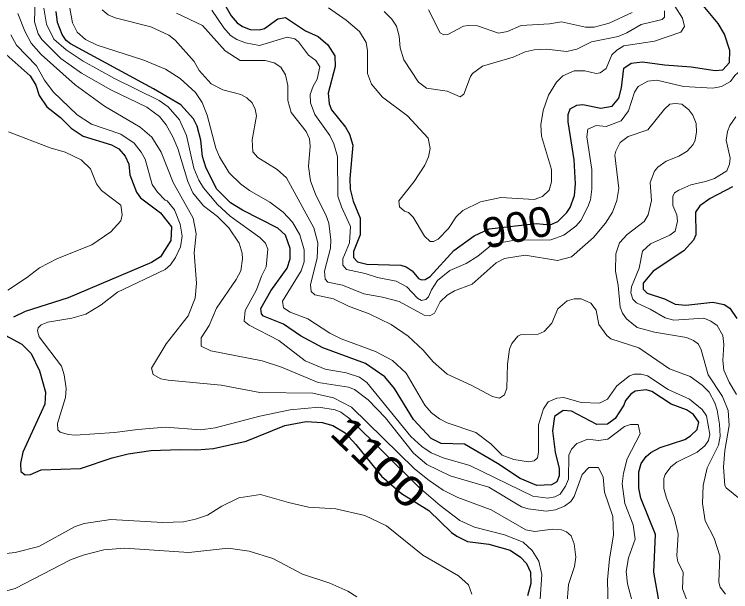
# Model space of a CAD drawing. Extents: x 265 to 291.4, y 7731.5 to 7759.6.
# Drawn here: x 283.424 to 285.338, y 7746.284 to 7747.826 of the extents above; entities that cross this region are included whole.
import ezdxf
from ezdxf.enums import TextEntityAlignment as Align

# ---------------------------------------------------------------- set-up
doc = ezdxf.new("R2010")
doc.units = 0
doc.header["$LTSCALE"] = 0.032
for name, color, linetype, lineweight in [('1', 7, 'Continuous', 25), ('2', 7, 'Continuous', 13), ('61', 7, 'Continuous', 13)]:
    doc.layers.add(name, color=color, linetype=linetype, lineweight=lineweight)

msp = doc.modelspace()

# ---------------------------------------------------------------- linework, layer by layer
at = {"layer": '1'}
for points in [[(283.9682, 7747.8833), (284.0032, 7747.8221), (284.0191, 7747.8037), (284.0334, 7747.7934), (284.0541, 7747.7855), (284.078, 7747.7847), (284.0923, 7747.7886), (284.1281, 7747.8141), (284.1488, 7747.8173), (284.2021, 7747.7823), (284.2355, 7747.7664), (284.2617, 7747.7449), (284.28, 7747.7155), (284.2816, 7747.6868), (284.2625, 7747.6153), (284.2649, 7747.5866), (284.2713, 7747.5707), (284.3087, 7747.5246), (284.3198, 7747.5055), (284.3286, 7747.4768), (284.3206, 7747.3877), (284.3214, 7747.3591), (284.3293, 7747.3273), (284.3484, 7747.2811), (284.3484, 7747.2366), (284.3301, 7747.1921), (284.3301, 7747.1761), (284.3405, 7747.165), (284.366, 7747.1586), (284.4567, 7747.1562), (284.471, 7747.1515), (284.4869, 7747.1411), (284.5036, 7747.1204), (284.5115, 7747.1165), (284.5219, 7747.118), (284.5354, 7747.126), (284.5982, 7747.1952), (284.6523, 7747.2342), (284.6932, 7747.253), (284.8184, 7747.2676), (284.8555, 7747.2636), (284.876, 7747.2722), (284.9005, 7747.2962), (284.9093, 7747.3098), (284.9212, 7747.3416), (284.9236, 7747.3734), (284.9196, 7747.4371), (284.9037, 7747.5389), (284.9037, 7747.5588), (284.9093, 7747.5739), (284.9276, 7747.5834), (284.9435, 7747.585), (284.9912, 7747.5755), (285.0214, 7747.581), (285.0397, 7747.6017), (285.0469, 7747.6296), (285.0524, 7747.6821), (285.0724, 7747.6956), (285.1026, 7747.6995), (285.1615, 7747.6908), (285.233, 7747.686), (285.2967, 7747.6757), (285.3174, 7747.6781), (285.3356, 7747.6972), (285.3364, 7747.7298), (285.3221, 7747.7728), (285.3046, 7747.8014), (285.2513, 7747.8666)], [(285.1479, 7746.2502), (285.1328, 7746.3361), (285.1376, 7746.4363), (285.0986, 7746.5334), (285.093, 7746.5604), (285.093, 7746.6034), (285.0994, 7746.6257), (285.1129, 7746.6448), (285.1248, 7746.6551), (285.1495, 7746.6686), (285.2163, 7746.6901), (285.2314, 7746.6996), (285.2489, 7746.7171), (285.2537, 7746.7362), (285.2394, 7746.7569), (285.2203, 7746.7696), (285.179, 7746.7847), (285.128, 7746.8182), (285.1121, 7746.8229), (285.0835, 7746.8197), (285.0716, 7746.811), (285.0572, 7746.7943), (285.0532, 7746.7823), (285.0294, 7746.7458), (285.0095, 7746.7314), (284.9809, 7746.7306), (284.9133, 7746.7656), (284.891, 7746.7672), (284.8679, 7746.7514), (284.8623, 7746.7132), (284.8695, 7746.6559), (284.8798, 7746.6129), (284.8798, 7746.593), (284.8735, 7746.5771), (284.8592, 7746.5692), (284.8202, 7746.5676), (284.7756, 7746.5859), (284.7152, 7746.6256), (284.6269, 7746.6773), (284.5648, 7746.6797), (284.5378, 7746.6925), (284.4908, 7746.7434), (284.4399, 7746.8261), (284.4137, 7746.8572), (284.362, 7746.8929), (284.2482, 7746.9351), (284.1886, 7746.9669), (284.1432, 7746.9987), (284.0899, 7747.0194), (284.0843, 7747.0258), (284.0827, 7747.0401), (284.109, 7747.087), (284.1527, 7747.1475), (284.1607, 7747.173), (284.1607, 7747.2), (284.1488, 7747.2358), (284.1281, 7747.2549), (284.0334, 7747.3026), (284.0016, 7747.3225), (283.9642, 7747.3599), (283.9356, 7747.418), (283.9268, 7747.4466), (283.9221, 7747.4896), (283.9125, 7747.5269), (283.9022, 7747.5468), (283.8688, 7747.5842), (283.7956, 7747.6272), (283.5737, 7747.7473), (283.5625, 7747.756), (283.5514, 7747.772), (283.5386, 7747.8046), (283.5355, 7747.8332)], [(283.4018, 7747.7187), (283.4655, 7747.6614), (283.4814, 7747.6367), (283.4901, 7747.6089), (283.5108, 7747.5787), (283.5466, 7747.55), (283.5752, 7747.5221), (283.6071, 7747.5007), (283.6834, 7747.4776), (283.7025, 7747.4665), (283.72, 7747.4474), (283.7296, 7747.4259), (283.7319, 7747.3973), (283.7502, 7747.3512), (283.7606, 7747.336), (283.8147, 7747.2954), (283.8441, 7747.2581), (283.8417, 7747.2215), (283.8139, 7747.1785), (283.79, 7747.1626), (283.5673, 7747.0687), (283.4528, 7747.0321), (283.4209, 7747.017)], [(285.3436, 7747.3654), (285.284, 7747.3344), (285.2561, 7747.3145), (285.2442, 7747.2978), (285.245, 7747.2366), (285.2394, 7747.2223), (285.2132, 7747.1944), (285.1312, 7747.1403), (285.1042, 7747.1077), (285.1042, 7747.0918), (285.1153, 7747.0814), (285.1615, 7747.0663), (285.1901, 7747.052), (285.2187, 7747.0488), (285.2903, 7747.0568), (285.3206, 7747.0512), (285.3365, 7747.0409), (285.3547, 7747.0131)], [(283.3987, 7746.9685), (283.4432, 7746.9446), (283.4686, 7746.92), (283.4909, 7746.8739), (283.5068, 7746.8166), (283.5052, 7746.7848), (283.4464, 7746.6559), (283.44, 7746.6257), (283.4408, 7746.605), (283.4527, 7746.5954), (283.4671, 7746.597), (283.4957, 7746.6089), (283.6007, 7746.6129), (283.685, 7746.6416), (283.728, 7746.6519), (283.7884, 7746.6606), (283.8664, 7746.6638), (283.911, 7746.6622), (283.9555, 7746.6662), (284.043, 7746.6861), (284.1464, 7746.7275), (284.2037, 7746.7386), (284.2466, 7746.7354), (284.2753, 7746.7275), (284.3079, 7746.7076), (284.3368, 7746.6764), (284.4052, 7746.592), (284.4583, 7746.5462), (284.5314, 7746.5007), (284.5919, 7746.4419), (284.6062, 7746.4315), (284.6348, 7746.418), (284.6921, 7746.4109), (284.7494, 7746.3942), (284.7764, 7746.3759), (284.7923, 7746.3592), (284.8035, 7746.3353), (284.8043, 7746.3051), (284.7955, 7746.2725)]]:
    msp.add_lwpolyline(points, dxfattribs=at)
at = {"layer": '2'}
for points in [[(284.7796, 7746.5103), (284.6921, 7746.5628), (284.5887, 7746.593), (284.5258, 7746.6233), (284.4908, 7746.6535), (284.4153, 7746.7482), (284.3691, 7746.7959), (284.3326, 7746.8237), (284.3166, 7746.8301), (284.2355, 7746.8428), (284.1377, 7746.8834), (284.086, 7746.9001), (283.9491, 7746.9271), (283.9229, 7746.9399), (283.9229, 7746.9622), (283.9443, 7746.9948), (283.9642, 7747.0409), (284.0167, 7747.1173), (284.0287, 7747.1411), (284.0334, 7747.173), (284.0326, 7747.1881), (284.0247, 7747.2143), (283.9968, 7747.2557), (283.9666, 7747.2859), (283.9292, 7747.3145), (283.9006, 7747.3496), (283.8871, 7747.379), (283.8608, 7747.4673), (283.8473, 7747.4991), (283.829, 7747.5309), (283.8115, 7747.5532), (283.7781, 7747.5779), (283.6811, 7747.624), (283.6031, 7747.6685), (283.5482, 7747.7083), (283.4973, 7747.7584), (283.4869, 7747.7743), (283.4774, 7747.8062), (283.4798, 7747.9016)], [(283.5021, 7747.8428), (283.5092, 7747.7998), (283.5291, 7747.76), (283.5625, 7747.7314), (283.6071, 7747.7011), (283.6914, 7747.6542), (283.8107, 7747.5954), (283.8346, 7747.5786), (283.8648, 7747.5444), (283.8839, 7747.5023), (283.9038, 7747.4148), (283.9165, 7747.383), (283.9292, 7747.3623), (283.9666, 7747.3177), (284.0008, 7747.2867), (284.0796, 7747.2302), (284.0947, 7747.2143), (284.1011, 7747.1984), (284.0971, 7747.1515), (284.0843, 7747.1268), (284.0708, 7747.0902), (284.0406, 7747.0345), (284.0382, 7747.0067), (284.051, 7746.9956), (284.1305, 7746.9542), (284.2013, 7746.9001), (284.2546, 7746.8778), (284.3103, 7746.8683), (284.3461, 7746.8563), (284.366, 7746.842), (284.4837, 7746.698), (284.5131, 7746.671), (284.5378, 7746.6543), (284.5696, 7746.6408), (284.6412, 7746.6209), (284.8098, 7746.5389), (284.8496, 7746.5334), (284.8687, 7746.5366), (284.883, 7746.5437), (284.8973, 7746.5652), (284.9045, 7746.5843), (284.9061, 7746.6479), (284.9133, 7746.6646), (284.9276, 7746.6798), (284.9562, 7746.6909), (284.9849, 7746.6877), (285.0103, 7746.6909), (285.0549, 7746.7251), (285.0708, 7746.7299), (285.0914, 7746.7299), (285.0962, 7746.7052), (285.062, 7746.6384), (285.0517, 7746.6002), (285.0485, 7746.5716), (285.0556, 7746.5191), (285.0779, 7746.4618), (285.0827, 7746.4236), (285.0652, 7746.3743), (285.0588, 7746.3377), (285.0628, 7746.3043), (285.0827, 7746.2279)], [(285.0342, 7746.8333), (285.0087, 7746.7975), (284.988, 7746.7871), (284.9387, 7746.7887), (284.8926, 7746.8022), (284.8735, 7746.8007), (284.8504, 7746.7911), (284.8377, 7746.772), (284.825, 7746.7291), (284.825, 7746.6559), (284.8218, 7746.6416), (284.813, 7746.6328), (284.7979, 7746.6304), (284.7589, 7746.6368), (284.7279, 7746.6487), (284.6977, 7746.679), (284.6571, 7746.7092), (284.5808, 7746.7346), (284.5601, 7746.745), (284.5386, 7746.7617), (284.5211, 7746.7816), (284.471, 7746.8675), (284.4344, 7746.9009), (284.389, 7746.9256), (284.2976, 7746.959), (284.2673, 7746.9741), (284.2077, 7747.0123), (284.1607, 7747.0306), (284.1432, 7747.0417), (284.1408, 7747.06), (284.1902, 7747.1411), (284.1981, 7747.165), (284.1981, 7747.1968), (284.187, 7747.2366), (284.1671, 7747.2708), (284.1424, 7747.2971), (284.1066, 7747.3241), (284.0525, 7747.3551), (284.0279, 7747.3734), (283.9976, 7747.4029), (283.9722, 7747.445), (283.9626, 7747.4689), (283.9388, 7747.5564), (283.9253, 7747.5906), (283.9078, 7747.6168), (283.8672, 7747.655), (283.8274, 7747.6797), (283.7694, 7747.7035), (283.6453, 7747.7441), (283.6134, 7747.7592), (283.5912, 7747.7783), (283.5792, 7747.803), (283.5721, 7747.8428)], [(283.658, 7747.838), (283.6747, 7747.8245), (283.693, 7747.8165), (283.7884, 7747.7926), (283.8362, 7747.7704), (283.8537, 7747.7568), (283.9046, 7747.6996), (283.9173, 7747.6757), (283.9499, 7747.6407), (283.981, 7747.624), (284.0287, 7747.6121), (284.0446, 7747.6033), (284.0589, 7747.5898), (284.0676, 7747.5723), (284.0708, 7747.5548), (284.0589, 7747.4912), (284.0613, 7747.4585), (284.0748, 7747.4434), (284.1257, 7747.4116), (284.1512, 7747.3893), (284.2244, 7747.2557), (284.2347, 7747.2159), (284.2331, 7747.1746), (284.2156, 7747.1046), (284.2172, 7747.0855), (284.2268, 7747.0767), (284.2769, 7747.0656), (284.3166, 7747.0465), (284.3723, 7747.0258), (284.4312, 7746.9971), (284.4765, 7746.9661), (284.5163, 7746.9287), (284.5433, 7746.8977), (284.5808, 7746.8651), (284.6444, 7746.8357), (284.7017, 7746.8046), (284.7208, 7746.8007), (284.7335, 7746.8094), (284.7398, 7746.8277), (284.7422, 7746.8914), (284.747, 7746.9311), (284.7534, 7746.947), (284.7693, 7746.9661), (284.7764, 7746.9701), (284.8242, 7746.9717)], [(285.1615, 7747.5723), (285.1169, 7747.5174), (285.0644, 7747.4999), (285.0429, 7747.484), (285.031, 7747.4609), (285.0286, 7747.4498), (285.0397, 7747.3607), (285.0342, 7747.3289), (285.0222, 7747.2971), (285.0039, 7747.2684), (284.9721, 7747.2302), (284.9133, 7747.1785), (284.8751, 7747.1682), (284.7892, 7747.1825), (284.7335, 7747.1737), (284.7112, 7747.1618), (284.6476, 7747.1053), (284.5998, 7747.087), (284.5808, 7747.0759), (284.5616, 7747.0576), (284.5465, 7747.0274), (284.5346, 7747.0202), (284.5187, 7747.0226), (284.4519, 7747.0584), (284.4073, 7747.0703), (284.358, 7747.0791), (284.3007, 7747.1022), (284.2618, 7747.1109), (284.2546, 7747.1189), (284.253, 7747.1403), (284.2689, 7747.2016), (284.2697, 7747.2239), (284.2641, 7747.2684), (284.2562, 7747.2907), (284.2291, 7747.3432), (284.2148, 7747.3814), (284.21, 7747.4196), (284.214, 7747.4737), (284.2124, 7747.4935), (284.2037, 7747.5126), (284.1631, 7747.5635), (284.1544, 7747.5962), (284.1544, 7747.6359), (284.1488, 7747.6646), (284.1361, 7747.6853), (284.1178, 7747.6964), (284.0939, 7747.7027), (284.0271, 7747.7027), (283.9873, 7747.7282), (283.9261, 7747.7958), (283.8569, 7747.8292)], [(283.9515, 7747.8372), (283.9833, 7747.7903), (284.0016, 7747.7696), (284.0183, 7747.7584), (284.0414, 7747.7497), (284.0788, 7747.7425), (284.1528, 7747.7648), (284.1735, 7747.7608), (284.183, 7747.7528), (284.21, 7747.7171), (284.2291, 7747.7027), (284.2403, 7747.686), (284.2331, 7747.6526), (284.222, 7747.6343), (284.214, 7747.6121), (284.2148, 7747.5898), (284.2267, 7747.558), (284.2673, 7747.5023), (284.2777, 7747.48), (284.2872, 7747.4466), (284.288, 7747.34), (284.2983, 7747.3114), (284.3222, 7747.2589), (284.3198, 7747.2159), (284.3015, 7747.173), (284.3015, 7747.1563), (284.3111, 7747.1443), (284.3612, 7747.134), (284.3946, 7747.1228), (284.4439, 7747.1133), (284.4726, 7747.0982), (284.5012, 7747.068), (284.5123, 7747.0616), (284.5235, 7747.064), (284.5306, 7747.0711), (284.5386, 7747.0902), (284.5545, 7747.1149), (284.5879, 7747.1419), (284.6317, 7747.1602), (284.6627, 7747.1801), (284.7017, 7747.2119), (284.7618, 7747.2226), (284.8578, 7747.2239), (284.8926, 7747.2358), (284.9244, 7747.2597), (284.9379, 7747.2748), (284.957, 7747.3114), (284.9634, 7747.3305), (284.9673, 7747.3591), (284.9673, 7747.4116), (284.9538, 7747.4991), (284.9562, 7747.519), (284.9785, 7747.5293), (285.0055, 7747.5261), (285.0461, 7747.5413), (285.0652, 7747.5683), (285.0811, 7747.6184), (285.0914, 7747.6335), (285.1169, 7747.6479), (285.1408, 7747.6502), (285.2124, 7747.6335), (285.2903, 7747.6288), (285.3142, 7747.6335)], [(285.1893, 7747.8475), (285.21, 7747.8157), (285.2147, 7747.7934), (285.2052, 7747.7783), (285.1344, 7747.7544), (285.0525, 7747.7417), (285.0342, 7747.7306), (285.0206, 7747.7179), (285.0055, 7747.6813), (284.9896, 7747.6701), (284.9785, 7747.6677), (284.9483, 7747.6749), (284.9196, 7747.6749), (284.8894, 7747.6614), (284.8727, 7747.6447), (284.8512, 7747.6105), (284.8369, 7747.5691), (284.8305, 7747.5309), (284.8329, 7747.5007), (284.8592, 7747.4116), (284.8592, 7747.3782), (284.8536, 7747.3559), (284.8353, 7747.3392), (284.813, 7747.3312), (284.7239, 7747.3368), (284.6698, 7747.3249), (284.6221, 7747.3018), (284.6046, 7747.2851), (284.5839, 7747.2541), (284.5569, 7747.2255), (284.5442, 7747.2191), (284.5354, 7747.2191), (284.5203, 7747.2334), (284.49, 7747.2843), (284.4773, 7747.2962), (284.4662, 7747.3002), (284.4527, 7747.3114), (284.4511, 7747.3281), (284.4924, 7747.3798), (284.5211, 7747.4227), (284.5306, 7747.445), (284.5354, 7747.4673), (284.5298, 7747.4951), (284.4741, 7747.5548), (284.4081, 7747.6049), (284.3787, 7747.6391), (284.3676, 7747.6678), (284.3676, 7747.7282), (284.3636, 7747.7505), (284.3461, 7747.7799), (284.3103, 7747.8109), (284.2633, 7747.8435)], [(284.4121, 7747.834), (284.4328, 7747.8133), (284.4455, 7747.7942), (284.4519, 7747.768), (284.4551, 7747.7362), (284.4646, 7747.7043), (284.5036, 7747.6447), (284.5251, 7747.6288), (284.5808, 7747.6208), (284.615, 7747.6057), (284.6253, 7747.6129), (284.6428, 7747.6598), (284.6484, 7747.6678), (284.6746, 7747.6876), (284.7573, 7747.7115), (284.7892, 7747.7258), (284.813, 7747.7314), (284.8449, 7747.733), (284.9005, 7747.7266), (284.9276, 7747.733), (284.9666, 7747.7529), (285.0374, 7747.7672), (285.0612, 7747.7767), (285.0994, 7747.799), (285.1551, 7747.8125), (285.1614, 7747.8189), (285.1614, 7747.8356)], [(285.0755, 7747.8308), (285.0135, 7747.8022), (284.9737, 7747.7918), (284.9499, 7747.7918), (284.8862, 7747.8061), (284.8544, 7747.8006), (284.778, 7747.7958), (284.7414, 7747.7799), (284.7176, 7747.7759), (284.6619, 7747.795), (284.638, 7747.7966), (284.6245, 7747.7942), (284.5823, 7747.7719), (284.5712, 7747.7711), (284.5616, 7747.7767), (284.5306, 7747.838)], [(283.4329, 7747.8284), (283.4519, 7747.7807), (283.4686, 7747.7489), (283.4949, 7747.7187), (283.5864, 7747.6375), (283.6644, 7747.581), (283.7598, 7747.5245), (283.7908, 7747.4983), (283.8163, 7747.4577), (283.8481, 7747.3766), (283.9014, 7747.2811), (283.9093, 7747.2398), (283.9046, 7747.1889), (283.9109, 7747.1077), (283.907, 7747.068), (283.8879, 7747.0202), (283.8298, 7746.9455), (283.79, 7746.881), (283.7948, 7746.8635), (283.8155, 7746.8524), (283.8346, 7746.8484), (283.9762, 7746.8357), (284.0796, 7746.8158), (284.2212, 7746.8142), (284.2769, 7746.8015), (284.3246, 7746.7768), (284.4932, 7746.6121), (284.5322, 7746.5803), (284.5696, 7746.5549), (284.6094, 7746.535), (284.6985, 7746.5024), (284.7908, 7746.4491), (284.8146, 7746.4443), (284.8624, 7746.4506), (284.8862, 7746.4491), (284.8997, 7746.4435), (284.9117, 7746.4324), (284.9204, 7746.4117), (284.9244, 7746.3759), (284.9212, 7746.3504), (284.9053, 7746.3027), (284.9005, 7746.2454)], [(283.615, 7747.025), (283.6556, 7747.0496), (283.6993, 7747.0839), (283.8266, 7747.1443), (283.8409, 7747.157), (283.8545, 7747.1761), (283.868, 7747.2048), (283.872, 7747.2334), (283.8672, 7747.2652), (283.8513, 7747.3034), (283.8322, 7747.3281), (283.8266, 7747.3297), (283.8059, 7747.3511), (283.7916, 7747.3718), (283.7733, 7747.4387), (283.763, 7747.4577), (283.7439, 7747.4816), (283.7081, 7747.5063), (283.6294, 7747.5325), (283.5912, 7747.5572), (283.5275, 7747.6192), (283.5044, 7747.6503), (283.483, 7747.6884), (283.4289, 7747.7441), (283.4138, 7747.7712)], [(285.3142, 7747.6335), (285.338, 7747.6463), (285.3492, 7747.6622), (285.3659, 7747.6773), (285.4017, 7747.6773), (285.4136, 7747.6685), (285.4232, 7747.6391)], [(285.2466, 7747.5341), (285.237, 7747.5564), (285.2267, 7747.5707), (285.2076, 7747.5858), (285.1901, 7747.5882), (285.1758, 7747.5858), (285.1615, 7747.5723)], [(285.3524, 7747.5524), (285.3364, 7747.5293), (285.3301, 7747.5134), (285.3261, 7747.4896), (285.3372, 7747.4418), (285.3357, 7747.4259), (285.3285, 7747.4076), (285.2951, 7747.3877), (285.2712, 7747.379), (285.2315, 7747.3702), (285.1996, 7747.3567), (285.1885, 7747.3488), (285.1837, 7747.3392), (285.1837, 7747.3153), (285.1941, 7747.2907), (285.1964, 7747.2732), (285.1901, 7747.2469), (285.1758, 7747.2358), (285.124, 7747.2127), (285.1026, 7747.1936), (285.0938, 7747.1475), (285.0731, 7747.0982), (285.0716, 7747.0823), (285.0771, 7747.0648), (285.0867, 7747.0552), (285.1233, 7747.0385), (285.163, 7747.0154), (285.1869, 7747.0091), (285.2665, 7747.0146), (285.2855, 7747.0067), (285.3023, 7746.9948), (285.3174, 7746.9677), (285.3205, 7746.9439), (285.3174, 7746.9009), (285.3205, 7746.8755), (285.3341, 7746.8436), (285.3539, 7746.8102)], [(285.3635, 7746.531), (285.3261, 7746.5612), (285.3229, 7746.5676), (285.319, 7746.6161), (285.3229, 7746.6607), (285.3341, 7746.7275), (285.3317, 7746.7673), (285.3166, 7746.8054), (285.2784, 7746.8627), (285.2593, 7746.9295), (285.2521, 7746.9447), (285.2386, 7746.955), (285.2203, 7746.9629), (285.1344, 7746.9765), (285.0883, 7746.9892), (285.0596, 7747.0123), (285.0493, 7747.0274), (285.0429, 7747.0441), (285.0381, 7747.1014), (285.0302, 7747.1396), (285.031, 7747.1865), (285.0413, 7747.2159), (285.062, 7747.2374), (285.1074, 7747.2724), (285.1177, 7747.2907), (285.1264, 7747.3289), (285.1233, 7747.3766), (285.1352, 7747.4068), (285.1439, 7747.418), (285.1662, 7747.4339), (285.1996, 7747.4474), (285.2219, 7747.4601), (285.2378, 7747.4784), (285.2434, 7747.4896), (285.2474, 7747.5118), (285.2466, 7747.5341)], [(283.4082, 7747.5118), (283.5196, 7747.4697), (283.5593, 7747.4577), (283.6023, 7747.437), (283.627, 7747.4132), (283.6429, 7747.3734), (283.6564, 7747.3551), (283.7081, 7747.3161), (283.7121, 7747.2907), (283.7081, 7747.274), (283.6818, 7747.2446), (283.6309, 7747.2103), (283.5387, 7747.1737), (283.4909, 7747.1491), (283.4559, 7747.122), (283.4058, 7747.0894)], [(284.8242, 7746.9717), (284.8401, 7746.9788), (284.86, 7747.0011), (284.8767, 7747.0393), (284.9013, 7747.0608), (284.9196, 7747.0656), (284.9387, 7747.0656)], [(284.9387, 7747.0656), (284.965, 7747.0544), (284.9785, 7747.0353), (284.9864, 7746.9971), (285.0071, 7746.9677), (285.0182, 7746.959), (285.093, 7746.9351), (285.175, 7746.8786), (285.2299, 7746.8587), (285.2625, 7746.8349), (285.2808, 7746.8166), (285.2959, 7746.7879), (285.3022, 7746.7689), (285.3086, 7746.7307), (285.3102, 7746.6989), (285.3062, 7746.675), (285.276, 7746.6145), (285.2649, 7746.5668), (285.2633, 7746.5191), (285.2704, 7746.4729), (285.2943, 7746.4268), (285.3094, 7746.3791), (285.307, 7746.3091), (285.3102, 7746.2955), (285.3245, 7746.2772)], [(283.4901, 7746.9645), (283.4854, 7746.9805), (283.4869, 7746.9884), (283.4957, 7746.9964), (283.5132, 7747.0035), (283.5768, 7747.0139), (283.615, 7747.025)], [(284.8265, 7746.2247), (284.8337, 7746.3297), (284.8258, 7746.3655), (284.8082, 7746.3934), (284.7836, 7746.4157), (284.7335, 7746.4355), (284.6539, 7746.4562), (284.6142, 7746.4737), (284.5617, 7746.5135), (284.506, 7746.562), (284.3206, 7746.745), (284.296, 7746.7633), (284.2816, 7746.7696), (284.2371, 7746.7768), (284.1607, 7746.7696), (284.0796, 7746.7521), (283.9603, 7746.7211), (283.9221, 7746.7163), (283.8266, 7746.7227), (283.7534, 7746.7171), (283.6914, 7746.7084), (283.5864, 7746.702), (283.5673, 7746.7036), (283.5458, 7746.71), (283.5402, 7746.7163), (283.5386, 7746.733), (283.5601, 7746.8023), (283.5625, 7746.8261), (283.5569, 7746.8627), (283.5498, 7746.8858), (283.4901, 7746.9645)], [(285.2283, 7746.7975), (285.171, 7746.8237), (285.1161, 7746.8603), (285.0994, 7746.8651), (285.0803, 7746.8643), (285.0676, 7746.8603), (285.0342, 7746.8333)], [(285.2291, 7746.2407), (285.21, 7746.2916), (285.2116, 7746.3353), (285.1972, 7746.3632), (285.1941, 7746.3791), (285.198, 7746.4371), (285.1877, 7746.4825), (285.167, 7746.5334), (285.1599, 7746.5588), (285.1599, 7746.5859), (285.163, 7746.5962), (285.1781, 7746.6169), (285.1949, 7746.6296), (285.249, 7746.6559), (285.2696, 7746.6734), (285.2792, 7746.6877), (285.2824, 7746.7036), (285.2736, 7746.7537), (285.2625, 7746.7704), (285.2283, 7746.7975)], [(285.0111, 7746.2391), (285.0087, 7746.3154), (285.0143, 7746.3711), (285.0254, 7746.4348), (285.023, 7746.4841), (285.0015, 7746.5493), (284.9976, 7746.5891), (284.9849, 7746.6153), (284.9594, 7746.6153), (284.9411, 7746.597), (284.9204, 7746.5382)], [(283.4018, 7746.3854), (283.4257, 7746.3878), (283.4893, 7746.4045), (283.5864, 7746.4578), (283.6103, 7746.4658), (283.6819, 7746.4761), (283.8203, 7746.4682), (283.876, 7746.4705), (283.9078, 7746.4769), (283.9396, 7746.488), (283.9778, 7746.5119), (284.0239, 7746.5342), (284.0812, 7746.5429), (284.156, 7746.5214), (284.2101, 7746.5095), (284.2832, 7746.5047), (284.3604, 7746.4872), (284.4185, 7746.4594), (284.5155, 7746.3814), (284.611, 7746.3258), (284.6372, 7746.3019), (284.6468, 7746.2772)], [(284.9204, 7746.5382), (284.9109, 7746.5246), (284.8942, 7746.5119), (284.8703, 7746.5024), (284.8449, 7746.4984), (284.7971, 7746.5047), (284.7796, 7746.5103)], [(283.3621, 7746.2748), (283.4257, 7746.2923), (283.5737, 7746.3687), (283.6071, 7746.3814), (283.6628, 7746.3958), (283.7184, 7746.3997), (283.8903, 7746.3886), (283.9953, 7746.3997), (284.051, 7746.3918), (284.1146, 7746.3719), (284.1941, 7746.3305), (284.2673, 7746.3059), (284.3151, 7746.2852), (284.3389, 7746.2701)]]:
    msp.add_lwpolyline(points, dxfattribs=at)

# ---------------------------------------------------------------- texts
at = {"layer": '61'}
for s, rotation, width, p in [('900', 12.031, 1.05, (284.7761, 7747.2188)), ('1100', 316.056, 1.25, (284.3695, 7746.6009))]:
    msp.add_text(s, height=0.08, rotation=rotation, dxfattribs=dict(at, width=width)).set_placement(p, align=Align.CENTER)

doc.saveas('drawing.dxf')
